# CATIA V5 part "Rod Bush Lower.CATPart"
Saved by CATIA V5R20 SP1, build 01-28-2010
Part number: Rod Nush Lower
Bounding box of the stored display mesh (mm): x -7.5 to 7.5, y -7.312 to 7.312, z -12 to 12
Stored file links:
  D:\v5_r20\psrt_files_downloaded\c13-catia-v5r20-prt\c13-catia-v5r20-figr-13-41\Part & Asm files\Rod Bush Lower.CATPart
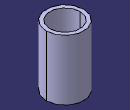
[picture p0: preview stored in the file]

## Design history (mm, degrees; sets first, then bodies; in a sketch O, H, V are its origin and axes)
Body1 (main body)
  Sketch1 on xy-plane, origin (0, 0, 0), H (1, 0, 0), V (0, 1, 0)
    circle A1 centre (0, 0) radius 6
    circle A2 centre (0, 0) radius 7.5
    point P1 (0, 0)
    radius A2 = 7.5
    radius A1 = 6
    coincidence: P1 H
    concentricity: A1 A2
  Pad1: profile Sketch1, direction (0, 0, 1), length 12, mirrored extent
